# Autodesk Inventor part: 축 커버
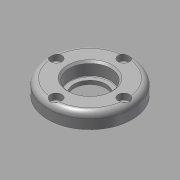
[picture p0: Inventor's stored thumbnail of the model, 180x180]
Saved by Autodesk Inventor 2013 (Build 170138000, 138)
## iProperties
Created: 2015-10
Part Number: 축 커버
Document SubType Name: Modeling
Designer: mdu
Density: 7.86 g/cm^3
Material: 강철, 연강
Mass: 76.1259 g
Surface Area: 48.0703 cm^2
Volume: 9.68523 cm^3
Author: mdu
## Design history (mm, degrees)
sketch "스케치1"
  geometry: C1 r 22.355 at (0, 0) reference; C2 r 14 at (0, 0) reference; C3 r 1.23 at (0, 18) reference; 1 further point
extrude "돌출1" new body sketch "스케치1" distance "d0" = 8; taper "d1" = 0 deg
sketch "스케치2"
  geometry: C1 r 14 at (0, 0) reference; 1 further point
extrude "돌출2" join sketch "스케치2" distance "d2" = 3; taper "d3" = 0 deg
hole "구멍1" diameter "d6" = 17; stored, may be unused: countersink angle "d10" = 90 deg, drill point angle "d12" = 118 deg; dims "d4" = 10, "d5" = 10, "d7" = 6, "d8" = 23, "d9" = 2, "d11" = 8
hole "구멍2" diameter "d15" = 22; stored, may be unused: countersink angle "d19" = 90 deg, drill point angle "d21" = 0 deg; dims "d13" = 10, "d14" = 10, "d16" = 6, "d17" = 25, "d18" = 2, "d20" = 7
fillet "모깎기1" dims "d22" = 3, "d23" = 0.3
chamfer "모따기1" distance "d24" = 1; stored, may be unused: second distance "d25" = 2, angle "d26" = 45 deg
sketch "스케치3"
  geometry: 2 further points
hole "구멍3" sketch "스케치3" at (0, 18) diameter "d27" = 3.4; stored, may be unused: countersink angle "d31" = 90 deg, drill point angle "d33" = 118 deg; dims "d28" = 6, "d29" = 6, "d30" = 3.3, "d32" = 7
node "솔리드1"
pattern_circular "원형 패턴1" dims angle "d35" = 360 deg
node "참조1"
node "참조2"
node "참조3"
